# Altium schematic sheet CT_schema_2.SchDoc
size 288 x 169 mm
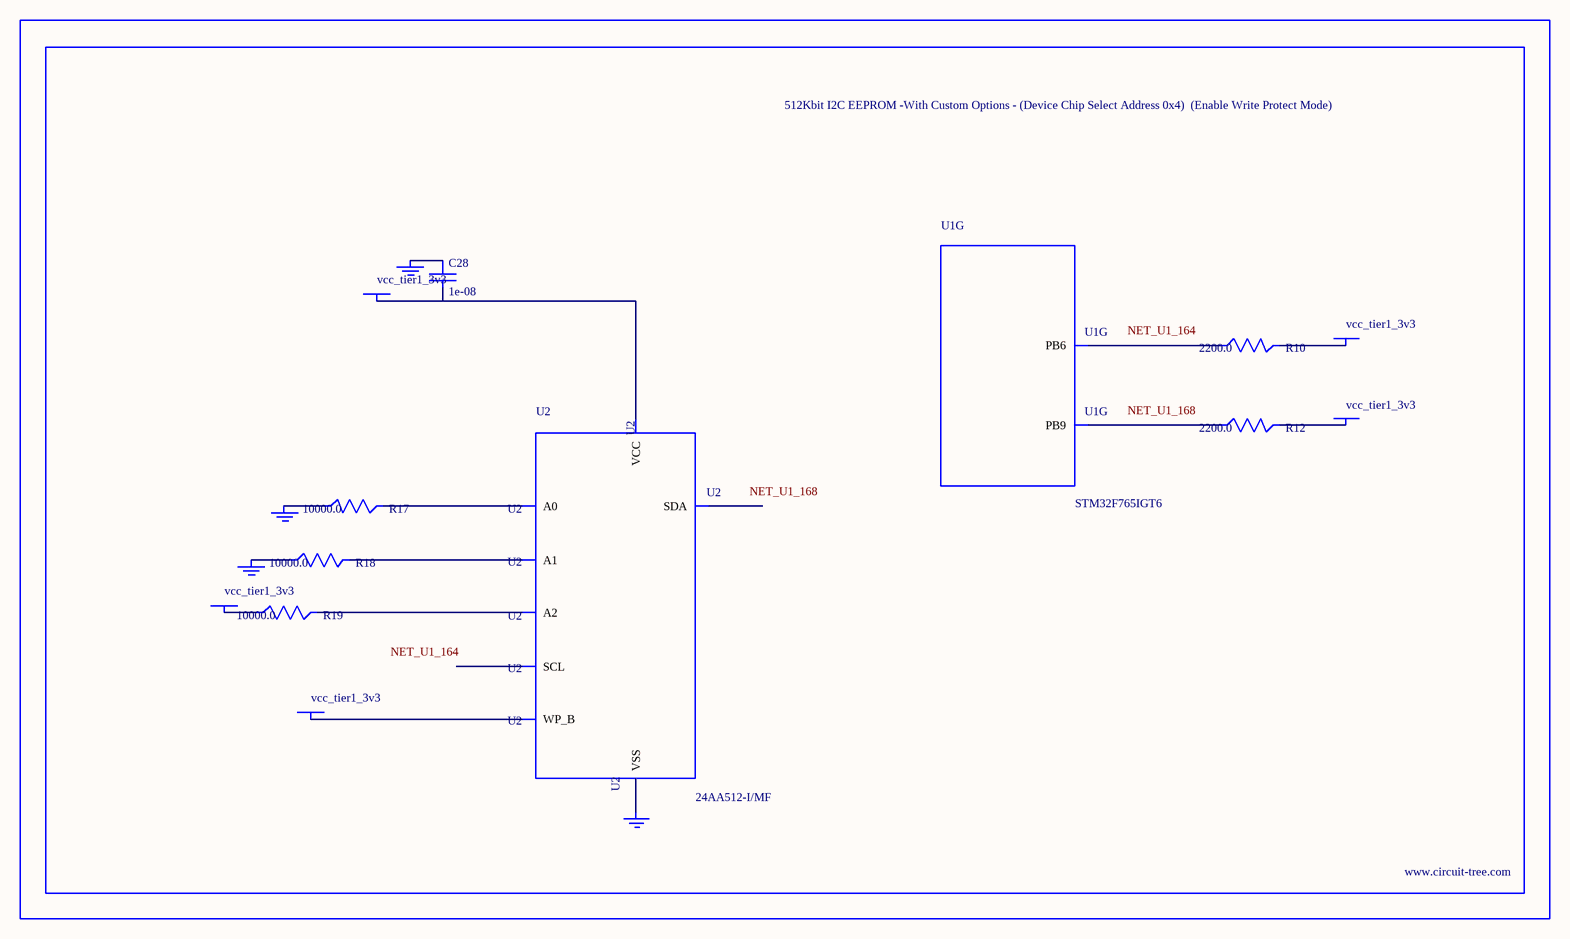
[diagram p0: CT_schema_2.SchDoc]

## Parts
BORDER1  (no value)
C28  1e-08  [C0402]
GND_INSTANCE_1_0  (no value)
GND_INSTANCE_1_1  (no value)
GND_INSTANCE_1_2  (no value)
GND_INSTANCE_1_3  (no value)
POWER_INSTANCE_1_0  vcc_tier1_3v3
POWER_INSTANCE_1_1  vcc_tier1_3v3
POWER_INSTANCE_1_2  vcc_tier1_3v3
POWER_INSTANCE_1_3  vcc_tier1_3v3
POWER_INSTANCE_1_4  vcc_tier1_3v3
R10  2200.0  [R0603]
R12  2200.0  [R0603]
R17  10000.0  [R0603]
R18  10000.0  [R0603]
R19  10000.0  [R0603]
U1  STM32F765IGT6  [LQFP176]  (part G of 14)
U2  24AA512-I/MF  [DFN8-S]

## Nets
NetC28_1: C28.1 GND_INSTANCE_1_2.0(GND)
NetC28_2: C28.2 POWER_INSTANCE_1_2.0(PWR) U2.8(VCC)
NetGND_INSTANCE_1_0_0: GND_INSTANCE_1_0.0(GND) R17.1
NetGND_INSTANCE_1_1_0: GND_INSTANCE_1_1.0(GND) R18.1
NetGND_INSTANCE_1_3_0: GND_INSTANCE_1_3.0(GND) U2.4(VSS)
NetPOWER_INSTANCE_1_0_0: POWER_INSTANCE_1_0.0(PWR) R19.1
NetPOWER_INSTANCE_1_1_0: POWER_INSTANCE_1_1.0(PWR) U2.7(WP_B)
NetPOWER_INSTANCE_1_3_0: POWER_INSTANCE_1_3.0(PWR) R10.2
NetPOWER_INSTANCE_1_4_0: POWER_INSTANCE_1_4.0(PWR) R12.2
NetR10_1: R10.1 U1.164(PB6)
NetR12_1: R12.1 U1.168(PB9)
NetR17_2: R17.2 U2.1(A0)
NetR18_2: R18.2 U2.2(A1)
NetR19_2: R19.2 U2.3(A2)

Not connected (* = marked no-connect by the designer): U2 5(SDA) 6(SCL)

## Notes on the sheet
- Labels drawn without touching a wire or pin: NET_U1_164, NET_U1_168

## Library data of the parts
BORDER1 = BORDER_PAGE1
C28 = C0402C103K3RAC
GND_INSTANCE_1_0-GND_INSTANCE_1_3 = GND
POWER_INSTANCE_1_0-POWER_INSTANCE_1_4 = PWR
R10 R12 = RC0603JR-072K2L
R17-R19 = RC0603JR-0710KL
